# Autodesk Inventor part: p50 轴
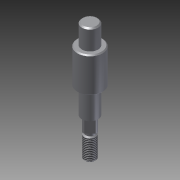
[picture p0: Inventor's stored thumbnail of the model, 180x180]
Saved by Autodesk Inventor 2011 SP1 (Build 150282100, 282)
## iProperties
Created: 2014-01
Part Number: p50 轴
Document SubType Name: Modeling
Designer: Administrator
Density: 1 g/cm^3
Author: Administrator
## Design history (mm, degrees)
sketch "草图1"
  geometry: C1 r 11 at (0, 0); 1 further point
  constraints: 1 centre point, 1 coincident
  dimensions: "d0" = 22 diameter of C1
extrude "拉伸1" new body sketch "草图1" distance "d1" = 44; taper "d2" = 0 deg
feature "螺纹1" dims "d3" = 10, "d4" = 0
node "工作平面4"
sketch "草图2"
  geometry: C1 r 9.25 at (0, 0.653)
  constraints: 1 centre point
  dimensions: "d7" = 18.5 diameter of C1
extrude "拉伸2" join sketch "草图2" distance "d8" = 6; taper "d9" = 0 deg
node "工作平面1"
sketch "草图3"
  geometry: C1 r 13.5 at (0, 0); 1 further point
  constraints: 1 centre point, 1 coincident
  dimensions: "d11" = 27 diameter of C1
extrude "拉伸3" join sketch "草图3" distance "d12" = 25; taper "d13" = 0 deg
sketch "草图4"
  geometry: L1 (-15.556, 0)-(-2.244, -13.312); L2 (2.244, -13.312)-(13.312, -2.244); L3 (15.556, 0)-(2.244, 13.312); L4 (0, 15.556)-(-13.312, 2.244); A1 r 13.5 centre (0, 0) between (13.312, -2.244) and (13.312, 2.244); A2 r 13.5 centre (0, 0) between (-2.244, -13.312) and (2.244, -13.312); A3 r 13.5 centre (0, 0) between (2.244, 13.312) and (-2.244, 13.312); A4 r 13.5 centre (0, 0) between (-13.312, 2.244) and (-13.312, -2.244); 3 further points
  constraints: 8 end point, 8 point on circle, 4 centre point, 3 point on line, 2 parallel, 1 coincident, 1 horizontal alignment, 1 perpendicular, 1 vertical alignment, 2 other
  dimensions: "d15" = 22 distance of L3.start L4.start; "d16" = 22 distance of L4.start L1.start
extrude "拉伸4" cut sketch "草图4" distance "d18" = 25; taper "d19" = 0 deg
node "工作平面2"
sketch "草图5"
  geometry: C1 r 16 at (0, 0); 1 further point
  constraints: 1 centre point, 1 coincident
  dimensions: "d21" = 32 diameter of C1
extrude "拉伸5" join sketch "草图5" distance "d22" = 50; taper "d23" = 0 deg
node "工作平面3"
sketch "草图6"
  geometry: C1 r 25 at (0, 0); 1 further point
  constraints: 1 centre point, 1 coincident
  dimensions: "d25" = 50 diameter of C1
extrude "拉伸6" join sketch "草图6" distance "d26" = 70; taper "d27" = 0 deg
node "工作平面5"
sketch "草图7"
  geometry: C1 r 23 at (0, 0) reference; C2 r 16 at (0, 0)
  constraints: 1 centre point, 1 coincident
  dimensions: "d30" = 32 diameter of C2
extrude "拉伸7" join sketch "草图7" distance "d31" = 40; taper "d32" = 0 deg
chamfer "倒角1" distance "d34" = 2.5; stored, may be unused: second distance "d35" = 2, angle "d36" = 45 deg
chamfer "倒角2" distance "d37" = 2; stored, may be unused: second distance "d38" = 2, angle "d39" = 45 deg
chamfer "倒角3" distance "d40" = 2; stored, may be unused: second distance "d41" = 2, angle "d42" = 45 deg
fillet "圆角7" dims "d43" = 3
chamfer "倒角4" distance "d44" = 2; stored, may be unused: second distance "d45" = 2, angle "d46" = 45 deg
chamfer "倒角5" distance "d47" = 2; stored, may be unused: second distance "d48" = 2, angle "d49" = 45 deg
node "工作平面6"
sketch "草图8"
  geometry: L1 (25, 127)-(25, 193) reference; L2 (16, 195)-(16, 232.5) reference; L3 (25, 193)-(-25, 193) reference; L4 (-23, 195)-(23, 195) reference; L5 (-25, 127)-(25, 127) reference; L6 (23, 125)-(-23, 125) reference; L7 (25, 127)-(23, 125) reference; L8 (16, 75)-(16, 122) reference; L9 (16, 122)-(-16, 122) reference; L10 (-7, 141)-(-7, 186); L11 (0, 193)-(5.143, 192.967); L12 (7, 186)-(7, 141); A1 r 3 centre (19, 122) between (19, 125) and (16, 122) reference; A2 r 7 centre (0, 141) between (-7, 141) and (7, 141); A3 r 7 centre (0, 186) between (7, 186) and (-7, 186); 3 further points
  constraints: 6 end point, 5 point on circle, 2 centre point, 1 midpoint, 1 parallel, 1 vertical alignment
  dimensions: "d51" = 14 distance of L10.end L11.end; "d52" = 52 distance of L11.end L12.end; "d55" = 9 distance from line of L6 point (0, 134); "d56" = 14 diameter of A2; "d57" = 14 diameter of A3
extrude "拉伸8" cut sketch "草图8" distance "d58" = 40; taper "d59" = 0 deg
sketch "草图9"
  geometry: L1 (16, 75)-(16, 122) reference; L2 (23, 125)-(-23, 125) reference; L3 (-25, 127)-(25, 127) reference; L4 (16, 89)-(13, 89); L5 (13, 89)-(16.006, 92.507); L6 (16.006, 92.507)-(16, 92.5); L7 (16, 92.5)-(16, 89); L8 (13, 89)-(16, 92.5); L9 (16, 92.5)-(16, 89); 1 further point
  constraints: 12 end point, 2 collinear, 2 point on line, 1 parallel
  dimensions: "d60" = 36 distance between parallel lines of L2 L4
revolve "旋转1" sketch "草图9" stored, may be unused: angle "d63" = 90 deg
node "实体1"
other parameters: "d17" = 27, "d20" = 75, "d24" = 125, "d50" = -19.5, "d61" = 3, "d62" = 3.5
